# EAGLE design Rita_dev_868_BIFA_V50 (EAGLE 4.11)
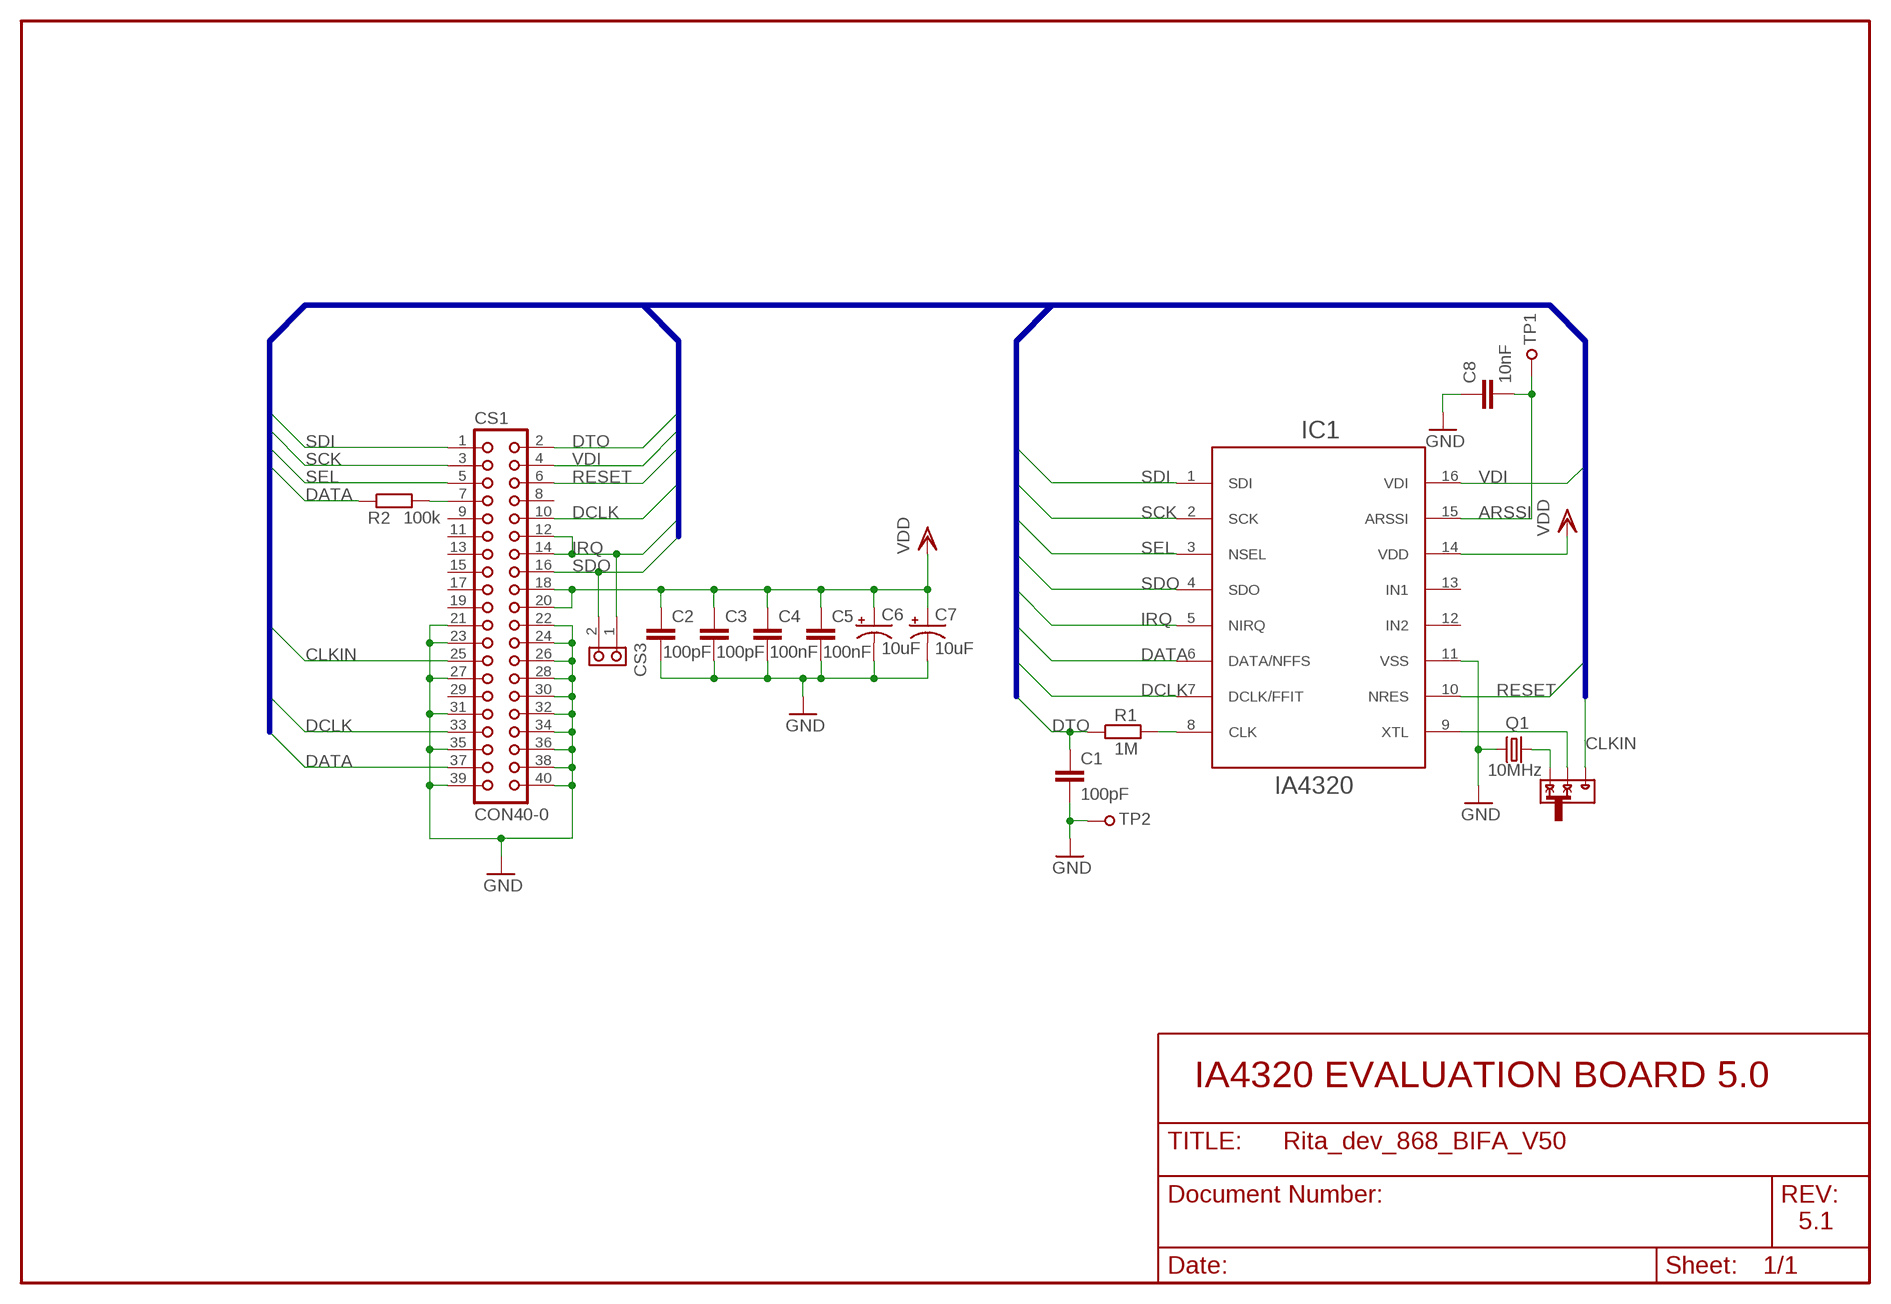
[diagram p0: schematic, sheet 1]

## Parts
C1  100pF  C-EUC0603  [C0603]
C2  100pF  C-EUC0603  [C0603]
C3  100pF  C-EUC0603  [C0603]
C4  100nF  C-EUC0603  [C0603]
C5  100nF  C-EUC0603  [C0603]
C6  10uF  CPOL-USA/3216-18R  [A/3216-18R]
C7  10uF  CPOL-USA/3216-18R  [A/3216-18R]
C8  10nF  C-EUC0603  [C0603]
CS1  CON40-0  [PANDUIT-057-040-0-INTEGRATION]
CS3  CRS-2  [CRS-2]
IC1  IA4320  RITATSSOP  [TSSOP-16]
Q1  10MHz  CRYTALSM49  [SM49]
R1  1M  R-EU_R0603  [R0603]
R2  100k  R-EU_R0603  [R0603]
SW1  SWITCH-RETRET  [SWITCH]
TP1  TESTPOINT  TESTPOINT39MIL  [TESTPOINT1,0]
TP2  TESTPOINT39MIL  [TESTPOINT1,0]

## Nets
ARSSI: C8.2 IC1.15(ARSSI) TP1.1
CLKIN: CS1.25 SW1.1
DATA: CS1.37 IC1.6(DATA/NFFS) R2.1
DCLK: CS1.10 CS1.33 IC1.7(DCLK/FFIT)
DTO: C1.1 CS1.2 R1.1
GND: C1.2 C2.2 C3.2 C4.2 C5.2 C6.- C7.- C8.1 CS1.21 CS1.22 CS1.23 CS1.24 CS1.26 CS1.27 CS1.28 CS1.30 CS1.31 CS1.32 CS1.34 CS1.35 CS1.36 CS1.38 CS1.39 CS1.40 IC1.11(VSS) Q1.2 TP2.1
IRQ: CS1.12 CS1.14 CS3.1(A) IC1.5(NIRQ)
N$1: CS1.7 R2.2
N$3: IC1.8(CLK) R1.2
N$4: IC1.9(XTL) SW1.2
N$6: Q1.1 SW1.3
RESET: CS1.6 IC1.10(NRES)
SCK: CS1.3 IC1.2(SCK)
SDI: CS1.1 IC1.1(SDI)
SDO: CS1.16 CS3.2(B) IC1.4(SDO)
SEL: CS1.5 IC1.3(NSEL)
VDD: C2.1 C3.1 C4.1 C5.1 C6.+ C7.+ CS1.18 CS1.20 IC1.14(VDD)
VDI: CS1.4 IC1.16(VDI)
Unconnected: CS1.8 CS1.9 CS1.11 CS1.13 CS1.15 CS1.17 CS1.19 CS1.29 IC1.12(IN2) IC1.13(IN1)

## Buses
B$1

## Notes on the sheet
- IA4320 EVALUATION BOARD 5.0
- 5.1

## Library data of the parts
C1-C5 C8 = rcl:C-EU: CAPACITOR, European symbol
C6 C7 = rcl:CPOL-US: POLARIZED CAPACITOR, American symbol
CS1 = lve:CON40
CS3 = lve:CRS-2: 2.54mm-es tuskesor krimpelheto csatlakozohoz
IC1 = lve:RITA: RITA
Q1 = crystal:CRYTAL: CRYSTAL
R1 R2 = rcl:R-EU_: RESISTOR, European symbol
SW1 = jumper:SWITCH-RET
TP1 TP2 = lve:TESTPOINT

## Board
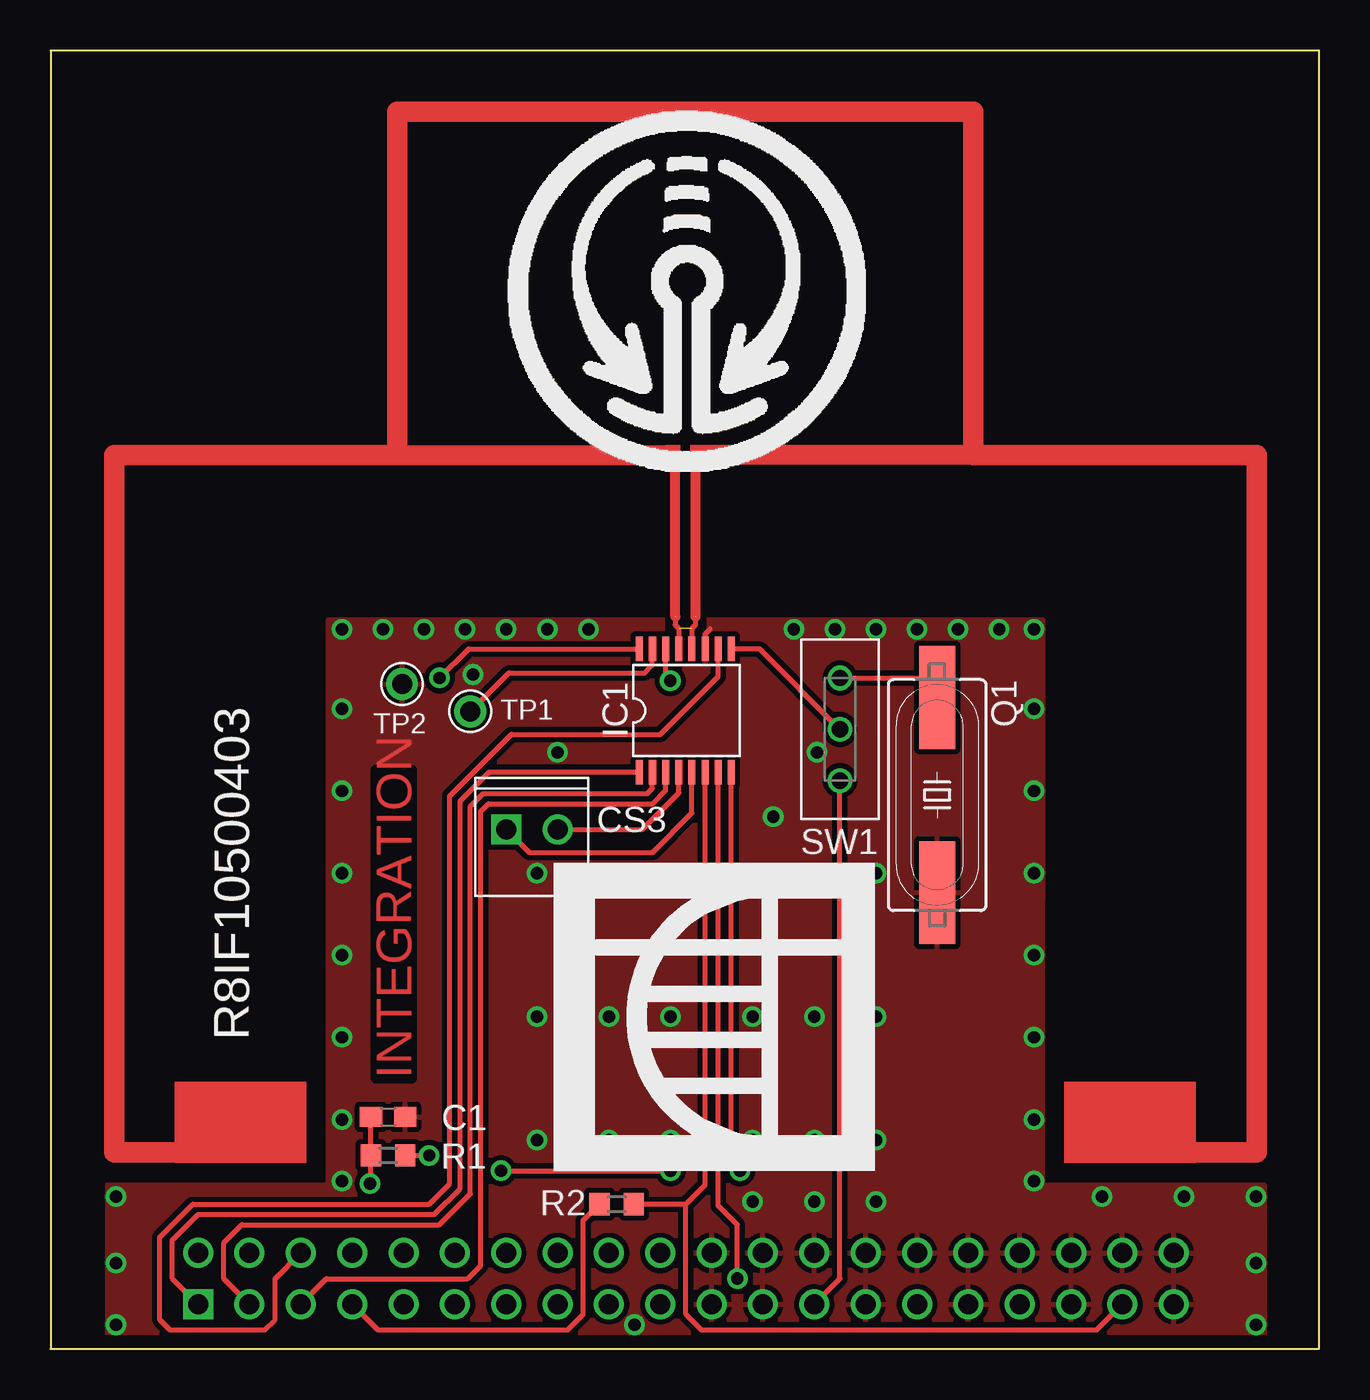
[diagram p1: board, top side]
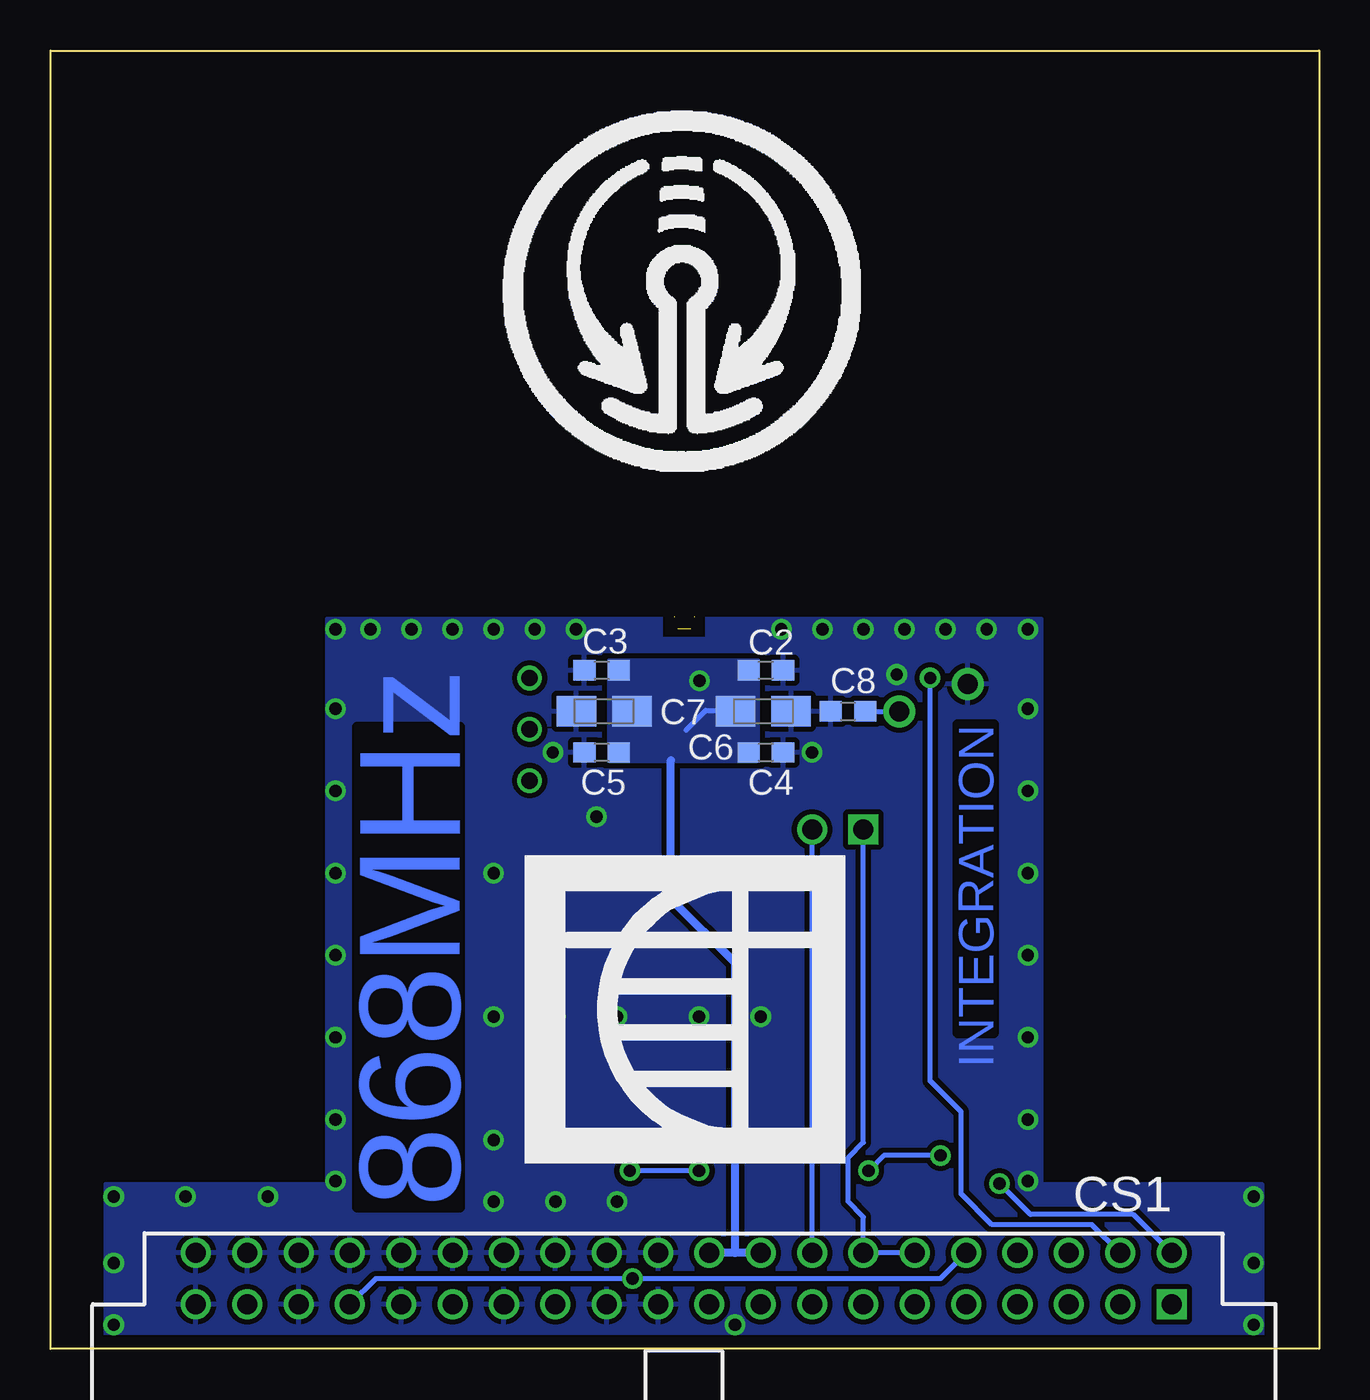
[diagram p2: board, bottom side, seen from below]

Size 62.75 x 64.25 mm. Coordinates in mm from the lower left corner, seen from the top.
Outline: 0,0 62.75,0 62.75,64.25 0,64.25 0,0
Copper layers (1*16): Top 0.035mm / dielectric 1.5mm / Bottom 0.035mm
Design rules "default_INTEGRATION": minimum track width 10mil, minimum drill 20mil, track to track 10mil, track to pad 10mil, pad to pad 10mil, via to via 10mil, smd to smd 10mil, copper to edge 25mil, drill to drill 8mil, minimum pad ring 8mil, minimum via ring 8mil, stop-mask expansion 4mil, vias tented up to drill 35mil, thermal gap 10mil
tRestrict: area 30.4,35.2 to 32.4,36.2; 3 lines
bRestrict: area 30.4,35.2 to 32.4,36.2; 7 lines

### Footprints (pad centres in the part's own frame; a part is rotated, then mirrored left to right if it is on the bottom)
C0603 = smd 1.1 x 1: 1 -0.85,0; 2 0.85,0
A/3216-18R = smd 1.95 x 1.5: + 1.375,0; - -1.375,0
PANDUIT-057-040-0-INTEGRATION = drill 0.991 square: 1 -24.13,-1.27 | drill 0.991 round: 2 -24.13,-3.81; 3 -21.59,-1.27; 4 -21.59,-3.81; 5 -19.05,-1.27; 6 -19.05,-3.81; 7 -16.51,-1.27; 8 -16.51,-3.81; 9 -13.97,-1.27; 10 -13.97,-3.81; 11 -11.43,-1.27; 12 -11.43,-3.81; 13 -8.89,-1.27; 14 -8.89,-3.81; 15 -6.35,-1.27; 16 -6.35,-3.81; 17 -3.81,-1.27; 18 -3.81,-3.81; 19 -1.27,-1.27; 20 -1.27,-3.81; 21 1.27,-1.27; 22 1.27,-3.81; 23 3.81,-1.27; 24 3.81,-3.81; 25 6.35,-1.27; 26 6.35,-3.81; 27 8.89,-1.27; 28 8.89,-3.81; 29 11.43,-1.27; 30 11.43,-3.81; 31 13.97,-1.27; 32 13.97,-3.81; 33 16.51,-1.27; 34 16.51,-3.81; 35 19.05,-1.27; 36 19.05,-3.81; 37 21.59,-1.27; 38 21.59,-3.81; 39 24.13,-1.27; 40 24.13,-3.81
CRS-2 = drill 0.991 square: 1 -1.27,0 | drill 0.991 round: 2 1.27,0
TSSOP-16 = smd 1.2 x 0.35: 1 -3.107,2.223; 2 -3.107,1.573; 3 -3.107,0.922; 4 -3.107,0.273; 5 -3.107,-0.378; 6 -3.107,-1.028; 7 -3.107,-1.677; 8 -3.107,-2.328; 9 2.993,-2.328; 10 2.993,-1.677; 11 2.993,-1.028; 12 2.993,-0.378; 13 2.993,0.273; 14 2.993,0.922; 15 2.993,1.573; 16 2.993,2.223
SM49 = smd 5.08 x 1.778: 1 -4.826,0; 2 4.826,0
R0603 = smd 1 x 1.1: 1 -0.85,0; 2 0.85,0
SWITCH = drill 0.813 round: 1 -2.54,0; 2 0,0; 3 2.54,0
TESTPOINT1,1 = drill 0.991 pad 1.575 round: 1 0,0

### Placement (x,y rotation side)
C1  16.7,11.48 0 top
C2  27.37,33.58 0 bottom
C3  35.49,33.58 180 bottom
C4  27.37,29.52 0 bottom
C5  35.49,29.52 180 bottom
C6  27.49,31.55 180 bottom
C7  35.37,31.55 0 bottom
C8  23.3,31.55 0 bottom
CS1  31.43,0.94 180 bottom
CS3  23.81,25.71 0 top
E$1  [RECEIVE-ICON]  31.5,52.75 0 top
E$2  [RECEIVE-ICON]  31.5,52.75 0 bottom
E$3  [LOGO_TOP_SHADE]  33.15,16.44 0 top
E$4  [LOGO_TOP_SHADE]  31.05,16.8 0 bottom
IC1  31.35,31.65 90 top
Q1  43.85,27.41 270 top
R1  16.7,9.58 0 top
R2  28,7.17 180 top
SW1  39.05,30.66 90 top
TP1  TESTPOINT  [TESTPOINT1,1]  20.76,31.55 0 top
TP2  TESTPOINT39MIL  [TESTPOINT1,1]  17.39,32.9 0 top

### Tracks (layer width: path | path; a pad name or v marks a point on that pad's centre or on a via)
ARSSI
  Top 0.254: IC1.15 29.78,33.83 29.4,33.46 22.67,33.46 TP1.1
  Bottom 0.254: C8.2 TP1.1
CLKIN
  Top 0.254: CS1.25 39.05,3.48 SW1.1
DATA
  Top 0.254: IC1.6 32.38,8.11 31.43,7.17 | 31.43,7.17 R2.1 | CS1.37 51.75,0.94 32.19,0.94 31.43,1.71 31.43,7.17
DCLK  (via drill 0.61 pad 1.02)
  Top 0.254: IC1.7 33.03,7.1 33.97,6.15 v33.97,3.48
  Bottom 0.254: CS1.33 46.67,3.48 v33.97,3.48 18.73,3.48 CS1.10
DTO  (via drill 0.61 pad 1.02)
  Top 0.254: C1.1 15.85,9.62 15.81,9.58 R1.1 15.85,8.22 v15.81,8.18
  Bottom 0.254: CS1.2 9.2,6.66 14.28,6.66 v15.81,8.18
GND  (via drill 0.61 pad 1.02)
  Top 0.254: 32.38,34.75 32.38,35.38 32.62,35.62
  other vias: 20.89,33.37 30.67,23.55 30.67,16.44 30.67,10.34 34.73,10.34 34.73,16.44 40.83,10.34 34.73,23.55 34.73,7.29 37.78,16.44 37.78,10.34 37.78,7.29 27.62,16.44 27.62,10.34 14.41,35.62 16.44,35.62 18.48,35.62 20.51,35.62 22.54,35.62 24.57,35.62 26.6,35.62 48.65,35.62 46.92,35.62 44.89,35.62 42.86,35.62 40.83,35.62 38.8,35.62 36.76,35.62 14.41,31.68 14.41,27.61 14.41,23.55 14.41,19.49 14.41,15.42 48.65,31.68 48.65,27.61 48.65,23.55 48.65,19.49 48.65,15.42 48.65,11.36 48.65,8.31 52,7.55 56.07,7.55 59.62,7.55 59.62,4.25 59.62,1.2 3.24,7.55 3.24,1.2 3.24,4.25 14.41,11.36 14.41,8.31 27.62,23.55 37.78,23.55 35.75,26.34 40.83,7.29 40.83,16.44 40.83,23.55 24.06,10.34 24.06,16.44 24.06,23.55 37.91,29.52 25.08,29.52 28.89,1.2
  pour Bottom (rank 2): 60.03,0.27 2.83,0.27 2.83,8.12 13.74,8.12 13.74,36.1 49.07,36.1 49.06,8.12 60.03,8.12
  pour Top (rank 2): 60.03,0.27 2.83,0.27 2.83,8.12 13.74,8.12 13.74,36.1 49.07,36.1 49.06,8.12 60.03,8.12
IRQ
  Top 0.254: IC1.5 31.72,26.51 29.78,24.57 23.68,24.57 CS3.1
  Bottom 0.254: CS1.12 CS1.14 22.54,6.53 23.3,7.29 23.3,9.45 22.54,10.22 CS3.1
N$1
  Top 0.254: R2.2 26.35,6.37 26.35,1.71 25.59,0.94 16.19,0.94 CS1.7
N$3  (via drill 0.61 pad 1.02)
  Top 0.254: IC1.8 33.67,9.24 v34.1,8.82 | v22.29,8.82 v30.67,8.82 | R1.2 v18.73,9.58
  Bottom 0.254: v30.67,8.82 v34.1,8.82 | v18.73,9.58 21.52,9.58 v22.29,8.82
N$4
  Top 0.254: IC1.9 35.07,34.64 SW1.2
N$6
  Top 0.254: Q1.1 43.88,32.24 43.88,33.2 SW1.3
N$37
  Top 1: 17.15,44.22 30.4,44.22 | 45.65,44.22 32.4,44.22
  Top 1.016: 50.65,9.72 59.65,9.72 59.65,44.22 45.65,44.22 45.65,61.22 17.15,61.22 17.15,44.22 3.15,44.22 3.15,9.72 12.15,9.72
RESET
  Top 0.254: CS1.6 11.11,3.48 11.11,1.45 10.6,0.94 5.9,0.94 5.4,1.45 5.4,5.52 7.05,7.17 18.73,7.17 19.75,8.18 19.75,27.36 22.79,30.41 30.16,30.41 33.03,33.27 IC1.10
S$1  (3 unrouted)
  Top 0.254: 31.08,34.65 31.08,35.65 30.9,35.83 30.9,36.23 | 31.72,34.65 31.72,35.65 31.9,35.83 31.9,36.23
  Top 0.5: 30.9,36.24 30.9,43.89 | 31.9,36.24 31.9,43.89
SCK
  Top 0.254: CS1.3 8.57,3.48 8.57,5.26 9.46,6.15 19.24,6.15 20.76,7.67 20.76,26.85 21.4,27.49 29.53,27.49 29.78,27.74 IC1.2
SDI
  Top 0.254: IC1.1 21.69,28.54 20.25,27.11 20.25,7.93 18.98,6.66 7.3,6.66 6.03,5.39 6.03,3.48 CS1.1
SDO
  Top 0.254: IC1.4 31.08,27.51 29.27,25.71 CS3.2
  Bottom 0.254: CS1.16 CS3.2
SEL
  Top 0.254: CS1.5 13.65,3.48 20.64,3.48 21.27,4.12 21.27,26.6 21.65,26.98 29.78,26.98 30.42,27.62 IC1.3
VDD  (via drill 0.61 pad 1.02)
  Top 0.254: v30.65,33.06 v30.66,33.06 30.67,33.08 30.42,33.32 IC1.14
  Bottom 0.254: 28.5,31.59 30.34,31.59 31.31,30.62
  Bottom 0.406: CS1.18 28.89,4.75 | 28.89,4.75 CS1.20 | 32.06,29.14 32.06,22.28 28.89,19.1 28.89,4.75
  pour Bottom (no thermals): 27.76,34.05 35.12,34.05 35.12,29.13 27.76,29.13
VDI  (via drill 0.61 pad 1.02)
  Top 0.254: IC1.16 20.68,34.64 v19.24,33.2
  Bottom 0.254: CS1.4 11.24,6.15 16.19,6.15 17.71,7.67 17.71,11.74 18.6,12.63 19.24,13.26 v19.24,33.2
(copper drawn outside any net)
  shapes: Top area x4

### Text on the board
Top: INTEGRATION
Bottom: INTEGRATION | 868MHz
tPlace: R8IF10500403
